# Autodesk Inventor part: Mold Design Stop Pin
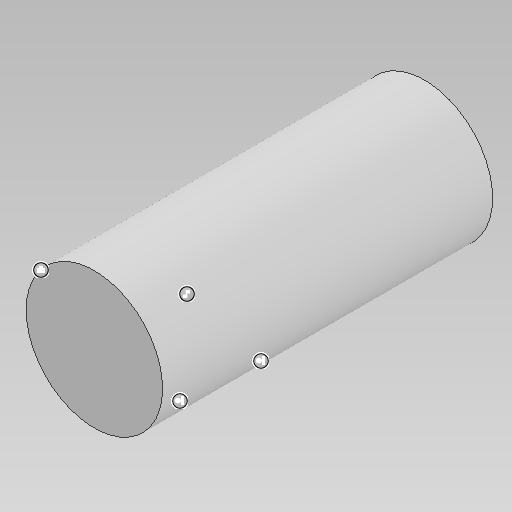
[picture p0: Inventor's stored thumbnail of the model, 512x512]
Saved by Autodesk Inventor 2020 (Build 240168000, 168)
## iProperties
Manager: www.cadconsulting.pl
Company: Fabian Stasiak CAD Consulting
Created: 2007-09
Part Number: Mold Design Stop Pin
Document SubType Name: Modeling
Designer: F.Stasiak
Density: 1 g/cm^3
Material: Generic
Appearance: Default
Catalog Web Link: www.expertbooks.pl
Author: F.Stasiak
Subject: Zbiór ćwiczeń. Autodesk Inventor 2020. Kurs Professional
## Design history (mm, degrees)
sketch "Sketch1"
  geometry: C1 r 4.132 at (0, 0); 1 further point
  constraints: 1 centre point, 1 coincident
  dimensions: "Diameter" = 8.26421 diameter of C1
extrude "Extrusion1" new body sketch "Sketch1" taper "d2" = 0 deg; stored distance "Height" = 20
body "Solid1"
other parameters: "d3" = 0, "d4" = 0, "d9" = 0, "d10" = 0
